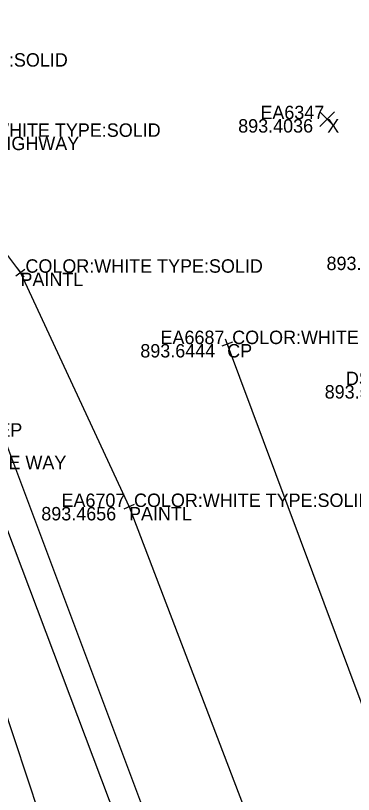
# Model space of a CAD drawing. Extents: x 179044 to 189691, y 286531 to 301257.
# Drawn here: x 180227.8 to 180258, y 300512.8 to 300582.5 of the extents above; entities that cross this region are included whole.
import ezdxf

# ---------------------------------------------------------------- set-up
doc = ezdxf.new("R2010")
doc.units = 0
for name, color, linetype in [('PM_X_Channelizing_Line', 7, 'Continuous'), ('PV_X_COP', 7, 'Continuous'), ('PV_X_EOP', 7, 'Continuous'), ('PV_X_Shoulder_Aggregate', 7, 'Continuous'), ('SV_X_Break_Lines', 7, 'Continuous'), ('SV_X_Random_Point', 7, 'Continuous'), ('SV_X_Shot_Marker', 7, 'Continuous'), ('SV_X_Text_Comment', 7, 'Continuous'), ('SV_X_Text_Description', 7, 'Continuous'), ('SV_X_Text_Elevation', 7, 'Continuous'), ('SV_X_Text_Name', 7, 'Continuous')]:
    doc.layers.add(name, color=color, linetype=linetype)

msp = doc.modelspace()

# ---------------------------------------------------------------- linework, layer by layer
at = {"layer": 'PM_X_Channelizing_Line'}
msp.add_lwpolyline([(180190.445, 300582.496), (180201.741, 300580.903), (180210.797, 300577.931), (180219.101, 300571.651), (180228.235, 300559.496), (180237.94, 300538.543), (180264.924, 300467.918), (180293.4, 300391.707), (180324.643, 300308.043), (180350.475, 300238.896)], dxfattribs=at)
at = {"layer": 'PV_X_COP'}
msp.add_lwpolyline([(180246.716, 300553.114), (180279.248, 300465.999), (180313.722, 300372.324), (180349.437, 300276.58), (180362.146, 300242.511)], dxfattribs=at)
at = {"layer": 'PV_X_EOP'}
msp.add_lwpolyline([(179371.146, 300578.051), (179477.168, 300579.528), (179563.012, 300579.455), (179660.626, 300579.907), (179772.349, 300580.843), (179883.302, 300581.216), (179986.953, 300581.659), (180080.461, 300581.624), (180131.142, 300581.875), (180152.421, 300580.897), (180177.372, 300581.245), (180192.481, 300580.813), (180205.116, 300578.916), (180211.895, 300576.366), (180217.061, 300570.924), (180226.256, 300546.032), (180252.64, 300475.662), (180284.891, 300388.784), (180312.046, 300315.753), (180341.998, 300235.308)], dxfattribs=at)
at = {"layer": 'PV_X_Shoulder_Aggregate'}
msp.add_lwpolyline([(179563.451, 300578.229), (179660.977, 300578.016), (179772.748, 300578.901), (179883.7, 300579.446), (179986.895, 300579.719), (180080.262, 300579.655), (180131.517, 300579.632), (180152.892, 300578.404), (180177.169, 300578.87), (180192.854, 300577.824), (180203.732, 300575.396), (180212.869, 300569.272), (180224.05, 300544.426), (180250.422, 300474.503), (180282.665, 300386.992), (180309.922, 300313.986), (180339.844, 300234.334)], dxfattribs=at)
at = {"layer": 'SV_X_Break_Lines'}
msp.add_lwpolyline([(180221.044, 300537.77), (180244.232, 300467.66), (180276.377, 300381.787), (180302.554, 300313.637), (180332.865, 300230.917)], dxfattribs=at)
at = {"layer": 'SV_X_Random_Point'}
for p, q in [((180254.988, 300572.563), (180256.321, 300573.898)), ((180254.988, 300573.898), (180256.321, 300572.563))]:
    msp.add_line(p, q, dxfattribs=at)
at = {"layer": 'SV_X_Shot_Marker'}
for p, q in [((180228.635, 300559.796), (180227.835, 300559.196)), ((180227.935, 300559.896), (180228.536, 300559.096)), ((180228.235, 300559.496), (180228.235, 300559.496)), ((180246.541, 300553.583), (180246.891, 300552.646)), ((180247.185, 300553.289), (180246.248, 300552.939)), ((180246.716, 300553.114), (180246.716, 300553.114)), ((180237.73, 300538.997), (180238.151, 300538.089)), ((180238.394, 300538.753), (180237.487, 300538.333)), ((180237.94, 300538.543), (180237.94, 300538.543))]:
    msp.add_line(p, q, dxfattribs=at)

# ---------------------------------------------------------------- texts
at = {"layer": 'SV_X_Text_Comment'}
for s, p in [('X', (180255.654, 300572.031)), ('PAINTL', (180228.235, 300558.296)), ('CP', (180246.716, 300551.914)), ('EP', (180226.256, 300544.832)), ('PAINTL', (180237.94, 300537.343))]:
    msp.add_text(s, height=1.2, dxfattribs=at).set_placement(p)
at = {"layer": 'SV_X_Text_Description'}
for s, p in [(' COLOR:WHITE TYPE:SOLID', (180210.797, 300577.931)), (' COLOR:WHITE TYPE:SOLID', (180219.101, 300571.651)), (' NOTE1:STOP NOTE2:DIVIDED HIGHWAY', (180202.013, 300570.461)), (' COLOR:WHITE TYPE:SOLID', (180228.235, 300559.496)), (' COLOR:WHITE TYPE:DASHED', (180246.716, 300553.114)), (' NOTE1:ONE WAY', (180218.514, 300541.92)), (' COLOR:WHITE TYPE:SOLID', (180237.94, 300538.543))]:
    msp.add_text(s, height=1.2, dxfattribs=at).set_placement(p)
at = {"layer": 'SV_X_Text_Elevation'}
for s, p in [('893.4036', (180247.699, 300572.031)), ('893.4495', (180255.596, 300559.732)), ('893.6444', (180238.95, 300551.914)), ('893.5661', (180255.431, 300548.241)), ('893.4656', (180230.099, 300537.343))]:
    msp.add_text(s, height=1.2, dxfattribs=at).set_placement(p)
at = {"layer": 'SV_X_Text_Name'}
for s, p in [('EA6347', (180249.683, 300573.231)), ('EA6687', (180240.754, 300553.114)), ('DS5213', (180257.328, 300549.441)), ('EA6707', (180231.903, 300538.543))]:
    msp.add_text(s, height=1.2, dxfattribs=at).set_placement(p)

doc.saveas('drawing.dxf')
